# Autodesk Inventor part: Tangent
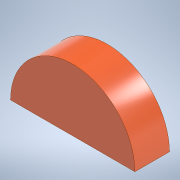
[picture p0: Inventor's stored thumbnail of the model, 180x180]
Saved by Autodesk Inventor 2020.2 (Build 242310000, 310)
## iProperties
Created: 2020-01
Part Number: Tangent
Material: Phenolic Resin
Document SubType Name: Modeling
Designer: thira
Density: 1.38 g/cm^3
Appearance: Smooth - Light Orange
Author: thira
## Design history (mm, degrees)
sketch "Sketch1"
  geometry: L1 (-18, 0)-(18, 0); A1 r 18 centre (0, 0) between (18, 0) and (-18, 0); 3 further points
  constraints: 3 coincident, 2 end point, 2 point on circle, 1 centre point, 1 horizontal, 1 midpoint
  dimensions: "d0" = 18 radius of A1
extrude "Extrusion1" new body sketch "Sketch1" distance "d1" = 10; taper "d2" = 0 deg
body "Solid1"
